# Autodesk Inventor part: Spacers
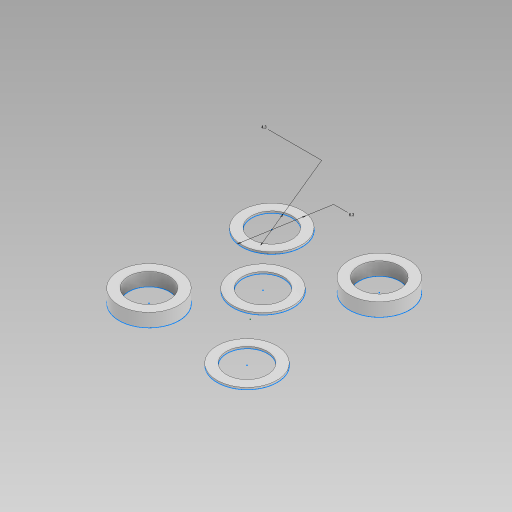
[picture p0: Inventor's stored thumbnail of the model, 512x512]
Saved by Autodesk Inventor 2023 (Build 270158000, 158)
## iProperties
Created: 2024-05
Part Number: Spacers
Material: 一般
Document SubType Name: Modeling
Designer: kumagai
Density: 1 g/cm^3
Appearance: 既定
Author: kumagai
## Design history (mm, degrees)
sketch "スケッチ1"
  geometry: C1 r 2.15 at (7.044, -9.316); C2 r 3.15 at (7.044, -9.316); C3 r 2.15 at (1.97, -3.312); C4 r 3.15 at (1.97, -3.312); C5 r 2.15 at (-4.004, 4.343); C6 r 3.15 at (-4.004, 4.343); C7 r 2.15 at (-4.364, -9.226); C8 r 3.15 at (-4.364, -9.226); C9 r 2.15 at (6.804, 3.863); C10 r 3.15 at (6.804, 3.863); 1 further point
  constraints: 10 centre point, 8 equal radius, 5 coincident
  dimensions: "d0" = 4.3 diameter of C1; "d1" = 6.3 diameter of C2
extrude "押し出し1" new body sketch "スケッチ1" distance "d2" = 0.2; taper "d3" = 0 deg
extrude "押し出し2" join sketch "スケッチ1" distance "d4" = 0.2; taper "d5" = 0 deg
extrude "押し出し3" join sketch "スケッチ1" distance "d6" = 1.4; taper "d7" = 0 deg
node "ソリッド1"
